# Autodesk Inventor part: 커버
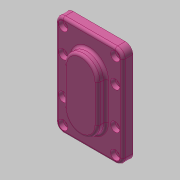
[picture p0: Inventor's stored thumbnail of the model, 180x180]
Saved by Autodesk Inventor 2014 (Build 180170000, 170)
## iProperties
Created: 2019-03
Part Number: 커버
Material: 알루미늄 6061
Document SubType Name: Modeling
Designer: mduedu
Density: 1 g/cm^3
Appearance: 분홍색
Author: mduedu
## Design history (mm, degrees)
sketch "스케치1"
  geometry: L1 (-60, 40)-(60, 40); L2 (60, 40)-(60, -40); L3 (60, -40)-(-60, -40); L4 (-60, -40)-(-60, 40); L5 (-60, 40)-(60, -40); L6 (60, 40)-(-60, -40); 1 further point
  constraints: 12 end point, 2 midpoint, 2 parallel, 1 horizontal, 1 perpendicular
  dimensions: "d59" = 120 distance of L2.end L3.end; "d60" = 80 distance of L1.end L2.end
extrude "돌출1" new body sketch "스케치1" distance "d4" = 12; taper "d5" = 0 deg
sketch "스케치2"
  geometry: L1 (-20, -22)-(20, -22); L2 (20, -22)-(20, 22); L3 (20, 22)-(-20, 22); L4 (-20, 22)-(-20, -22); L5 (-20, -22)-(20, 22); L6 (20, -22)-(-20, 22); 3 further points
  constraints: 12 end point, 4 midpoint, 2 horizontal alignment, 2 parallel, 1 horizontal, 1 perpendicular, 4 other
  dimensions: "d6" = 40 distance between parallel lines of L2 L4; "d8" = 44 distance between parallel lines of L1 L3
extrude "돌출2" join sketch "스케치2" distance "d9" = 10; taper "d10" = 0 deg
fillet "모깎기1" dims "d11" = 9
fillet "모깎기2" dims "d12" = 3
sketch "스케치3"
  geometry: L1 (-31, -60)-(31, -60) reference; L2 (-40, 51)-(-40, -51) reference; L3 (31, 60)-(-31, 60) reference; L4 (40, -51)-(40, 51) reference; L5 (-17, -22)-(-17, 22) reference; L6 (17, 22)-(17, -22) reference; L7 (-31, 51)-(31, 51); L8 (31, 51)-(31, -51); L9 (31, -51)-(-31, -51); L10 (-31, -51)-(-31, 51); A1 r 9 centre (31, -51) between (31, -60) and (40, -51) reference; A2 r 9 centre (-31, -51) between (-40, -51) and (-31, -60) reference; A3 r 9 centre (-31, 51) between (-31, 60) and (-40, 51) reference; A4 r 9 centre (31, 51) between (40, 51) and (31, 60) reference; A5 r 17 centre (0, -22) between (-17, -22) and (17, -22) reference; A6 r 17 centre (0, 22) between (17, 22) and (-17, 22) reference; 9 further points
  constraints: 8 end point, 4 coincident, 4 horizontal alignment, 4 point on line, 2 parallel, 1 horizontal, 1 perpendicular
hole "구멍2" sketch "스케치3" at (-31, 51), (31, 51), (31, -51), (-31, -51), (-31, 22), (-31, -22), (31, 22), (31, -22) diameter "d28" = 5.5; stored, may be unused: countersink angle "d32" = 90 deg, drill point angle "d34" = 118 deg; dims "d29" = 6, "d30" = 4, "d31" = 2, "d33" = 8
sketch "스케치9"
  geometry: L1 (40, -51)-(40, 51) reference; L2 (31, 60)-(-31, 60) reference; L3 (-40, 51)-(-40, -51) reference; L4 (-31, -60)-(31, -60) reference; L5 (23, -22)-(23, 22) reference; L6 (-23, 22)-(-23, -22) reference; C1 r 2.75 at (31, 22) reference; C2 r 2.75 at (-31, 22) reference; C3 r 2.75 at (31, -51) reference; C4 r 2.75 at (-31, 51) reference; C5 r 2.75 at (31, 51) reference; C6 r 2.75 at (-31, -51) reference; C7 r 2.75 at (-31, -22) reference; C8 r 2.75 at (31, -22) reference; A1 r 9 centre (31, -51) between (31, -60) and (40, -51) reference; A2 r 9 centre (31, 51) between (40, 51) and (31, 60) reference; A3 r 9 centre (-31, 51) between (-31, 60) and (-40, 51) reference; A4 r 9 centre (-31, -51) between (-40, -51) and (-31, -60) reference; A5 r 23 centre (0, -22) between (-23, -22) and (23, -22) reference; A6 r 23 centre (0, 22) between (23, 22) and (-23, 22) reference; 9 further points
  constraints: 8 coincident
hole "구멍4" sketch "스케치9" at (-31, 51), (31, 51), (31, 22), (-31, 22), (-31, -22), (31, -22), (31, -51), (-31, -51) diameter "d69" = 11; stored, may be unused: countersink angle "d73" = 90 deg, drill point angle "d75" = 0 deg; dims "d70" = 6, "d71" = 4, "d72" = 2, "d74" = 5.4
fillet "모깎기3" dims "d68" = 3
sketch "스케치6"
  geometry: C1 r 12.5 at (0, 22); 1 further point
  constraints: 1 centre point, 1 vertical alignment
  dimensions: "d43" = 25 diameter of C1; "d45" = 22 distance of C1.centre point (0, 0)
extrude "돌출5" cut sketch "스케치6" distance "d47" = 15; taper "d48" = 0 deg
node "솔리드1"
mirror "대칭1"
node "투영된 루프2"
node "투영된 루프3"
node "투영된 루프4"
